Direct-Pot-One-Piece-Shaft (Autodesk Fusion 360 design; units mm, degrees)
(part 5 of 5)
work_plane "WorkPlane12" AlongDistance 50.8 ExtraOffset 0
sketch "Clamp nut top installation slot" plane through (50.8, 0, 0) normal (1, 0, 0) x axis (0, 0, -1)
  line L1 (-73, -4.3) -> (-73, -6.9)
  line L2 (-78.1, -4.3) -> (-73, -4.3)
  line L3 (-78.1, -6.9) -> (-78.1, -4.3)
  line L4 (-73, -6.9) -> (-78.1, -6.9)
extrude "Extrude12" cut sketch "Clamp nut top installation slot" along normal blind 6.7
work_plane "WorkPlane1" AlongDistance -6.8 ExtraOffset 0
sketch "Sensor clamp captive M3 nut" plane through (0, -6.8, 0) normal (0, 1, 0) x axis (1, 0, 0)
  line L1 (55.7377, -75.75) -> (57.3254, -73)
  line L2 (52.5623, -75.75) -> (55.7377, -75.75)
  line L3 (50.9746, -73) -> (52.5623, -75.75)
  line L4 (52.5623, -70.25) -> (50.9746, -73)
  line L5 (55.7377, -70.25) -> (52.5623, -70.25)
  line L6 (57.3254, -73) -> (55.7377, -70.25)
extrude "Extrude1" new body sketch "Sensor clamp captive M3 nut" along normal blind 2.4 bodies "HARDWARE Sensor clamp captive M3 nut"
work_plane "WorkPlane2" AlongDistance -6.9 ExtraOffset 0
sketch "Thread envelope" plane through (0, -6.9, 0) normal (0, 1, 0) x axis (1, 0, 0)
  circle C1 centre (54.15, -73) radius 1.5
extrude "Extrude2" cut sketch "Thread envelope" along normal blind 2.6
work_plane "WorkPlane87" AlongDistance -24 ExtraOffset 0
sketch "Rear wall around captive block nuts" plane through (-24, 0, 0) normal (1, 0, 0) x axis (0, 0, -1)
  line L1 (-38, -73.9) -> (-38, -76)
  line L2 (-59, -73.9) -> (-38, -73.9)
  line L3 (-59, -76) -> (-59, -73.9)
  line L4 (-38, -76) -> (-59, -76)
extrude "Extrude87" add sketch "Rear wall around captive block nuts" along normal blind 48
work_plane "WorkPlane88" AlongDistance 1.1 ExtraOffset 0
sketch "Extend guide nut loading access through rear wall" plane through (1.1, 0, 0) normal (1, 0, 0) x axis (0, 0, -1)
  line L1 (-40.8, -73.8) -> (-40.8, -76.1)
  line L2 (-43.4, -73.8) -> (-40.8, -73.8)
  line L3 (-43.4, -76.1) -> (-43.4, -73.8)
  line L4 (-40.8, -76.1) -> (-43.4, -76.1)
extrude "Extrude88" cut sketch "Extend guide nut loading access through rear wall" along normal blind 5.8
work_plane "WorkPlane89" AlongDistance 17.1 ExtraOffset 0
sketch "Extend guide nut loading access through rear wall (1)" plane through (17.1, 0, 0) normal (1, 0, 0) x axis (0, 0, -1)
  line L1 (-40.8, -73.8) -> (-40.8, -76.1)
  line L2 (-43.4, -73.8) -> (-40.8, -73.8)
  line L3 (-43.4, -76.1) -> (-43.4, -73.8)
  line L4 (-40.8, -76.1) -> (-43.4, -76.1)
extrude "Extrude89" cut sketch "Extend guide nut loading access through rear wall (1)" along normal blind 5.8
work_plane "WorkPlane1" AlongDistance -33.9 ExtraOffset 0
sketch "Shaft cap captured M3 nut" plane through (-33.9, 0, 0) normal (1, 0, 0) x axis (0, 0, -1)
  line L1 (-67.75, 1.5877) -> (-65, 3.1754)
  line L2 (-67.75, -1.5877) -> (-67.75, 1.5877)
  line L3 (-65, -3.1754) -> (-67.75, -1.5877)
  line L4 (-62.25, -1.5877) -> (-65, -3.1754)
  line L5 (-62.25, 1.5877) -> (-62.25, -1.5877)
  line L6 (-65, 3.1754) -> (-62.25, 1.5877)
extrude "Extrude1" new body sketch "Shaft cap captured M3 nut" along normal blind 2.4 bodies "HARDWARE Shaft cap captured M3 nut"
work_plane "WorkPlane2" AlongDistance -34 ExtraOffset 0
sketch "Thread envelope" plane through (-34, 0, 0) normal (1, 0, 0) x axis (0, 0, -1)
  circle C1 centre (-65, 0) radius 1.5
extrude "Extrude2" cut sketch "Thread envelope" along normal blind 2.6
work_plane "WorkPlane21" AlongDistance -7.1 ExtraOffset 0
sketch "Rear-loaded cam hex nut" plane through (-7.1, 0, 0) normal (1, 0, 0) x axis (0, 0, -1)
  line L1 (-42.4442, 27.1302) -> (-39.5442, 28.8045)
  line L2 (-42.4442, 23.7815) -> (-42.4442, 27.1302)
  line L3 (-39.5442, 22.1072) -> (-42.4442, 23.7815)
  line L4 (-36.6442, 23.7815) -> (-39.5442, 22.1072)
  line L5 (-36.6442, 27.1302) -> (-36.6442, 23.7815)
  line L6 (-39.5442, 28.8045) -> (-36.6442, 27.1302)
extrude "Extrude21" cut sketch "Rear-loaded cam hex nut" along normal blind 11.7
work_plane "WorkPlane1" AlongDistance 2.1 ExtraOffset 0
sketch "Cam captured M3 nut -45" plane through (2.1, 0, 0) normal (1, 0, 0) x axis (0, 0, -1)
  line L1 (-42.2942, 27.0436) -> (-39.5442, 28.6313)
  line L2 (-42.2942, 23.8681) -> (-42.2942, 27.0436)
  line L3 (-39.5442, 22.2804) -> (-42.2942, 23.8681)
  line L4 (-36.7942, 23.8681) -> (-39.5442, 22.2804)
  line L5 (-36.7942, 27.0436) -> (-36.7942, 23.8681)
  line L6 (-39.5442, 28.6313) -> (-36.7942, 27.0436)
extrude "Extrude1" new body sketch "Cam captured M3 nut -45" along normal blind 2.4 bodies "HARDWARE Cam captured M3 nut -45"
work_plane "WorkPlane2" AlongDistance 2 ExtraOffset 0
sketch "Thread envelope" plane through (2, 0, 0) normal (1, 0, 0) x axis (0, 0, -1)
  circle C1 centre (-39.5442, 25.4558) radius 1.5
extrude "Extrude2" cut sketch "Thread envelope" along normal blind 2.6
work_plane "WorkPlane22" AlongDistance -7.1 ExtraOffset 0
sketch "Rear-loaded cam hex nut (1)" plane through (-7.1, 0, 0) normal (1, 0, 0) x axis (0, 0, -1)
  line L1 (-31.9, 1.6743) -> (-29, 3.3486)
  line L2 (-31.9, -1.6743) -> (-31.9, 1.6743)
  line L3 (-29, -3.3486) -> (-31.9, -1.6743)
  line L4 (-26.1, -1.6743) -> (-29, -3.3486)
  line L5 (-26.1, 1.6743) -> (-26.1, -1.6743)
  line L6 (-29, 3.3486) -> (-26.1, 1.6743)
extrude "Extrude22" cut sketch "Rear-loaded cam hex nut (1)" along normal blind 11.7
work_plane "WorkPlane1" AlongDistance 2.1 ExtraOffset 0
sketch "Cam captured M3 nut 0" plane through (2.1, 0, 0) normal (1, 0, 0) x axis (0, 0, -1)
  line L1 (-31.75, 1.5877) -> (-29, 3.1754)
  line L2 (-31.75, -1.5877) -> (-31.75, 1.5877)
  line L3 (-29, -3.1754) -> (-31.75, -1.5877)
  line L4 (-26.25, -1.5877) -> (-29, -3.1754)
  line L5 (-26.25, 1.5877) -> (-26.25, -1.5877)
  line L6 (-29, 3.1754) -> (-26.25, 1.5877)
extrude "Extrude1" new body sketch "Cam captured M3 nut 0" along normal blind 2.4 bodies "HARDWARE Cam captured M3 nut 0"
work_plane "WorkPlane2" AlongDistance 2 ExtraOffset 0
sketch "Thread envelope" plane through (2, 0, 0) normal (1, 0, 0) x axis (0, 0, -1)
  circle C1 centre (-29, 0) radius 1.5
extrude "Extrude2" cut sketch "Thread envelope" along normal blind 2.6
work_plane "WorkPlane23" AlongDistance -7.1 ExtraOffset 0
sketch "Rear-loaded cam hex nut (2)" plane through (-7.1, 0, 0) normal (1, 0, 0) x axis (0, 0, -1)
  line L1 (-42.4442, -23.7815) -> (-39.5442, -22.1072)
  line L2 (-42.4442, -27.1302) -> (-42.4442, -23.7815)
  line L3 (-39.5442, -28.8045) -> (-42.4442, -27.1302)
  line L4 (-36.6442, -27.1302) -> (-39.5442, -28.8045)
  line L5 (-36.6442, -23.7815) -> (-36.6442, -27.1302)
  line L6 (-39.5442, -22.1072) -> (-36.6442, -23.7815)
extrude "Extrude23" cut sketch "Rear-loaded cam hex nut (2)" along normal blind 11.7
work_plane "WorkPlane1" AlongDistance 2.1 ExtraOffset 0
sketch "Cam captured M3 nut 45" plane through (2.1, 0, 0) normal (1, 0, 0) x axis (0, 0, -1)
  line L1 (-42.2942, -23.8681) -> (-39.5442, -22.2804)
  line L2 (-42.2942, -27.0436) -> (-42.2942, -23.8681)
  line L3 (-39.5442, -28.6313) -> (-42.2942, -27.0436)
  line L4 (-36.7942, -27.0436) -> (-39.5442, -28.6313)
  line L5 (-36.7942, -23.8681) -> (-36.7942, -27.0436)
  line L6 (-39.5442, -22.2804) -> (-36.7942, -23.8681)
extrude "Extrude1" new body sketch "Cam captured M3 nut 45" along normal blind 2.4 bodies "HARDWARE Cam captured M3 nut 45"
work_plane "WorkPlane2" AlongDistance 2 ExtraOffset 0
sketch "Thread envelope" plane through (2, 0, 0) normal (1, 0, 0) x axis (0, 0, -1)
  circle C1 centre (-39.5442, -25.4558) radius 1.5
extrude "Extrude2" cut sketch "Thread envelope" along normal blind 2.6
work_plane "WorkPlane24" AlongDistance 15.2 ExtraOffset 0
sketch "Rotor side-loaded clamp nut" plane through (0, 15.2, 0) normal (0, 1, 0) x axis (1, 0, 0)
  line L1 (1.6743, -67.9) -> (3.3486, -65)
  line L2 (-1.6743, -67.9) -> (1.6743, -67.9)
  line L3 (-3.3486, -65) -> (-1.6743, -67.9)
  line L4 (-1.6743, -62.1) -> (-3.3486, -65)
  line L5 (1.6743, -62.1) -> (-1.6743, -62.1)
  line L6 (3.3486, -65) -> (1.6743, -62.1)
extrude "Extrude24" cut sketch "Rotor side-loaded clamp nut" along normal blind 2.6
work_plane "WorkPlane25" AlongDistance -7.1 ExtraOffset 0
sketch "Rotor clamp nut insertion from back face" plane through (-7.1, 0, 0) normal (1, 0, 0) x axis (0, 0, -1)
  line L1 (-62.1, 17.8) -> (-62.1, 15.2)
  line L2 (-67.9, 17.8) -> (-62.1, 17.8)
  line L3 (-67.9, 15.2) -> (-67.9, 17.8)
  line L4 (-62.1, 15.2) -> (-67.9, 15.2)
extrude "Extrude25" cut sketch "Rotor clamp nut insertion from back face" along normal blind 7.1
work_plane "WorkPlane1" AlongDistance 15.3 ExtraOffset 0
sketch "Rotor clamp captured M3 nut" plane through (0, 15.3, 0) normal (0, 1, 0) x axis (1, 0, 0)
  line L1 (1.5877, -67.75) -> (3.1754, -65)
  line L2 (-1.5877, -67.75) -> (1.5877, -67.75)
  line L3 (-3.1754, -65) -> (-1.5877, -67.75)
  line L4 (-1.5877, -62.25) -> (-3.1754, -65)
  line L5 (1.5877, -62.25) -> (-1.5877, -62.25)
  line L6 (3.1754, -65) -> (1.5877, -62.25)
extrude "Extrude1" new body sketch "Rotor clamp captured M3 nut" along normal blind 2.4 bodies "HARDWARE Rotor clamp captured M3 nut"
work_plane "WorkPlane2" AlongDistance 15.2 ExtraOffset 0
sketch "Thread envelope" plane through (0, 15.2, 0) normal (0, 1, 0) x axis (1, 0, 0)
  circle C1 centre (0, -65) radius 1.5
extrude "Extrude2" cut sketch "Thread envelope" along normal blind 2.6
work_plane "WorkPlane7" AlongDistance 180 ExtraOffset 0
sketch "Small grip socket insert lead-in" plane through (0, 0, 180) normal (0, 0, 1) x axis (1, 0, 0)
  line L1 (-7.4, 1.9) -> (-7.4, 0)
  line L2 (-7.2, 2.1) -> (-7.4, 1.9)
  line L3 (-7.2, 0) -> (-7.2, 2.1)
  line L4 (-7.4, 0) -> (-7.2, 0)
  line L5 (-6.2, 0) -> (-8.4, 0)
revolve "Revolve2" sketch "Small grip socket insert lead-in" AlongAngle 360
work_plane "WorkPlane8" AlongDistance 190 ExtraOffset 0
sketch "Small grip socket insert lead-in (1)" plane through (0, 0, 190) normal (0, 0, 1) x axis (1, 0, 0)
  line L1 (-7.4, 1.9) -> (-7.4, 0)
  line L2 (-7.2, 2.1) -> (-7.4, 1.9)
  line L3 (-7.2, 0) -> (-7.2, 2.1)
  line L4 (-7.4, 0) -> (-7.2, 0)
  line L5 (-6.2, 0) -> (-8.4, 0)
revolve "Revolve3" sketch "Small grip socket insert lead-in (1)" AlongAngle 360
ground "Pin164"
ground "Pin165"
ground "Pin166"
ground "Pin167"
ground "Pin168"
ground "Pin170"
ground "Pin171"
ground "Pin172"
ground "Pin173"
ground "Pin174"
ground "Pin175"
ground "Pin176"
ground "Pin177"
ground "Pin178"
ground "Pin179"
ground "Pin180"
ground "Pin181"
ground "Pin182"
ground "Pin183"
ground "Pin184"
ground "Pin185"
ground "Pin186"
ground "Pin187"
ground "Pin188"
ground "Pin189"
ground "Pin190"
ground "Pin191"
ground "Pin192"
ground "Pin193"
ground "Pin194"
ground "Pin195"
ground "Pin196"
ground "Pin197"
ground "Pin198"
ground "Pin199"
ground "Pin200"
ground "Pin201"
ground "Pin202"
ground "Pin203"
ground "Pin204"
ground "Pin205"
ground "Pin206"
ground "Pin207"
ground "Pin208"
ground "Pin209"
ground "Pin210"
ground "Pin211"
ground "Pin216"
ground "Pin217"
ground "Pin218"
ground "Pin219"
ground "Pin220"
ground "Pin221"
ground "Pin222"
ground "Pin223"
ground "Pin224"
ground "Pin225"
ground "Pin226"
ground "Pin227"
ground "Pin228"
ground "Pin229"
ground "Pin230"
ground "Pin231"
ground "Pin232"
ground "Pin233"
ground "Pin234"
ground "Pin235"
ground "Pin236"
ground "Pin237"
ground "Pin238"
ground "Pin239"
ground "Pin242"
ground "Pin243"
ground "Pin244"
ground "Pin245"
ground "Unpin246"
ground "Unpin247"
ground "Unpin248"
ground "Unpin249"
ground "Unpin250"
ground "Unpin252"
ground "Unpin253"
ground "Unpin254"
ground "Unpin255"
ground "Unpin256"
ground "Unpin257"
ground "Unpin258"
ground "Unpin259"
ground "Unpin260"
ground "Unpin261"
ground "Unpin262"
ground "Unpin263"
ground "Unpin264"
ground "Unpin265"
ground "Unpin266"
ground "Unpin267"
ground "Unpin268"
ground "Unpin269"
ground "Unpin270"
ground "Unpin271"
ground "Unpin272"
ground "Unpin273"
ground "Unpin274"
ground "Unpin275"
ground "Unpin276"
ground "Unpin277"
ground "Unpin278"
ground "Unpin279"
ground "Unpin280"
ground "Unpin281"
ground "Unpin282"
ground "Unpin283"
ground "Unpin284"
ground "Unpin285"
ground "Unpin286"
ground "Unpin287"
ground "Unpin288"
ground "Unpin289"
ground "Unpin290"
ground "Unpin291"
ground "Unpin292"
ground "Unpin293"
ground "Unpin298"
ground "Unpin299"
ground "Unpin300"
ground "Unpin301"
ground "Unpin302"
ground "Unpin303"
ground "Unpin304"
ground "Unpin305"
ground "Unpin306"
ground "Unpin307"
ground "Unpin308"
ground "Unpin309"
ground "Unpin310"
ground "Unpin311"
ground "Unpin312"
ground "Unpin313"
ground "Unpin314"
ground "Unpin315"
ground "Unpin316"
ground "Unpin317"
ground "Unpin318"
ground "Unpin319"
ground "Unpin320"
ground "Unpin321"
ground "Unpin324"
ground "Unpin325"
ground "Unpin326"
ground "Unpin327"
position "Position1"
ground "Pin328"
ground "Pin329"
ground "Pin330"
ground "Pin331"
ground "Pin332"
ground "Pin334"
ground "Pin335"
ground "Pin336"
ground "Pin337"
ground "Pin338"
ground "Pin339"
ground "Pin340"
ground "Pin341"
ground "Pin342"
ground "Pin343"
ground "Pin344"
ground "Pin345"
ground "Pin346"
ground "Pin347"
ground "Pin348"
ground "Pin349"
ground "Pin350"
ground "Pin351"
ground "Pin352"
ground "Pin353"
ground "Pin354"
ground "Pin355"
ground "Pin356"
ground "Pin357"
ground "Pin358"
ground "Pin359"
ground "Pin360"
ground "Pin361"
ground "Pin362"
ground "Pin363"
ground "Pin364"
ground "Pin365"
ground "Pin366"
ground "Pin367"
ground "Pin368"
ground "Pin369"
ground "Pin370"
ground "Pin371"
ground "Pin372"
ground "Pin373"
ground "Pin374"
ground "Pin375"
ground "Pin380"
ground "Pin381"
ground "Pin382"
ground "Pin383"
ground "Pin384"
ground "Pin385"
ground "Pin386"
ground "Pin387"
ground "Pin388"
ground "Pin389"
ground "Pin390"
ground "Pin391"
ground "Pin392"
ground "Pin393"
ground "Pin394"
ground "Pin395"
ground "Pin396"
ground "Pin397"
ground "Pin398"
ground "Pin399"
ground "Pin400"
ground "Pin401"
ground "Pin402"
ground "Pin403"
ground "Pin406"
ground "Pin407"
ground "Pin408"
ground "Pin409"
work_plane "WorkPlane85" AlongDistance 57.9 ExtraOffset 0
sketch "Trim former insert fill flush with carriage face" plane through (57.9, 0, 0) normal (1, 0, 0) x axis (0, 0, -1)
  line L1 (-62.9, -28) -> (-62.9, -28.2)
  line L2 (-67.1, -28) -> (-62.9, -28)
  line L3 (-67.1, -28.2) -> (-67.1, -28)
  line L4 (-62.9, -28.2) -> (-67.1, -28.2)
extrude "Extrude85" cut sketch "Trim former insert fill flush with carriage face" along normal blind 4.5
work_plane "WorkPlane86" AlongDistance 57.9 ExtraOffset 0
sketch "Trim former insert fill flush with carriage face (1)" plane through (57.9, 0, 0) normal (1, 0, 0) x axis (0, 0, -1)
  line L1 (-62.9, 28.2) -> (-62.9, 28)
  line L2 (-67.1, 28.2) -> (-62.9, 28.2)
  line L3 (-67.1, 28) -> (-67.1, 28.2)
  line L4 (-62.9, 28) -> (-67.1, 28)
extrude "Extrude86" cut sketch "Trim former insert fill flush with carriage face (1)" along normal blind 4.5
ground "Unpin411"
ground "Unpin412"
ground "Unpin413"
ground "Unpin414"
ground "Unpin415"
ground "Unpin416"
ground "Unpin417"
ground "Unpin418"
ground "Unpin419"
ground "Unpin420"
ground "Unpin421"
ground "Unpin422"
ground "Unpin423"
ground "Unpin424"
ground "Unpin429"
ground "Unpin430"
ground "Unpin431"
ground "Unpin432"
ground "Unpin433"
ground "Unpin434"
ground "Unpin435"
ground "Unpin436"
ground "Unpin439"
ground "Unpin440"
ground "Unpin441"
ground "Unpin442"
work_plane "WorkPlane1" AlongDistance -37.35 ExtraOffset 0
sketch "Continuous main journal shaft" plane through (-37.35, 0, 0) normal (1, 0, 0) x axis (0, 0, -1)
  circle C1 centre (-65, 0) radius 6
extrude "Extrude1" new body sketch "Continuous main journal shaft" along normal blind 74.7 bodies "P05 One-piece shaft with continuous print flat"
work_plane "WorkPlane2" AlongDistance -23.8 ExtraOffset 0
sketch "Central load-bearing shaft" plane through (-23.8, 0, 0) normal (1, 0, 0) x axis (0, 0, -1)
  circle C1 centre (-65, 0) radius 8
extrude "Extrude2" add sketch "Central load-bearing shaft" along normal blind 47.6
work_plane "WorkPlane3" AlongDistance -23.9 ExtraOffset 0
sketch "Preserved upper D drive flat" plane through (-23.9, 0, 0) normal (1, 0, 0) x axis (0, 0, -1)
  line L1 (-56, 9) -> (-56, 6.5)
  line L2 (-74, 9) -> (-56, 9)
  line L3 (-74, 6.5) -> (-74, 9)
  line L4 (-56, 6.5) -> (-74, 6.5)
extrude "Extrude3" cut sketch "Preserved upper D drive flat" along normal blind 47.8
work_plane "WorkPlane4" AlongDistance 37.35 ExtraOffset 0
sketch "Integral retaining shoulder" plane through (37.35, 0, 0) normal (1, 0, 0) x axis (0, 0, -1)
  circle C1 centre (-65, 0) radius 10
extrude "Extrude4" add sketch "Integral retaining shoulder" along normal blind 3
work_plane "WorkPlane5" AlongDistance 37.25 ExtraOffset 0
sketch "Preserved shoulder upper flat" plane through (37.25, 0, 0) normal (1, 0, 0) x axis (0, 0, -1)
  line L1 (-54, 11) -> (-54, 6.5)
  line L2 (-76, 11) -> (-54, 11)
  line L3 (-76, 6.5) -> (-76, 11)
  line L4 (-54, 6.5) -> (-76, 6.5)
extrude "Extrude5" cut sketch "Preserved shoulder upper flat" along normal blind 3.2
work_plane "WorkPlane6" AlongDistance 40.35 ExtraOffset 0
sketch "Integral Oldham input tongue" plane through (40.35, 0, 0) normal (1, 0, 0) x axis (0, 0, -1)
  line L1 (-63, 6.5) -> (-63, -8)
  line L2 (-67, 6.5) -> (-63, 6.5)
  line L3 (-67, -8) -> (-67, 6.5)
  line L4 (-63, -8) -> (-67, -8)
extrude "Extrude6" add sketch "Integral Oldham input tongue" along normal blind 3
work_plane "WorkPlane7" AlongDistance -37.5 ExtraOffset 0
sketch "Continuous underside print bed flat" plane through (-37.5, 0, 0) normal (1, 0, 0) x axis (0, 0, -1)
  line L1 (-54, -4.2) -> (-54, -10.2)
  line L2 (-76, -4.2) -> (-54, -4.2)
  line L3 (-76, -10.2) -> (-76, -4.2)
  line L4 (-54, -10.2) -> (-76, -10.2)
extrude "Extrude7" cut sketch "Continuous underside print bed flat" along normal blind 81
work_plane "WorkPlane8" AlongDistance -37.45 ExtraOffset 0
sketch "End cap M3 passage" plane through (-37.45, 0, 0) normal (1, 0, 0) x axis (0, 0, -1)
  circle C1 centre (-65, 0) radius 1.7
extrude "Extrude8" cut sketch "End cap M3 passage" along normal blind 6.8
work_plane "WorkPlane9" AlongDistance -37.45 ExtraOffset 0
sketch "Support-free screw-passage crown" plane through (-37.45, 0, 0) normal (1, 0, 0) x axis (0, 0, -1)
  line L1 (-66.2021, 1.2021) -> (-63.7979, 1.2021)
  line L2 (-65, 2.4042) -> (-66.2021, 1.2021)
  line L3 (-63.7979, 1.2021) -> (-65, 2.4042)
extrude "Extrude9" cut sketch "Support-free screw-passage crown" along normal blind 6.8
work_plane "WorkPlane10" AlongDistance -34 ExtraOffset 0
sketch "Captured cap nut pocket" plane through (-34, 0, 0) normal (1, 0, 0) x axis (0, 0, -1)
  line L1 (-67.9, 1.6743) -> (-65, 3.3486)
  line L2 (-67.9, -1.6743) -> (-67.9, 1.6743)
  line L3 (-65, -3.3486) -> (-67.9, -1.6743)
  line L4 (-62.1, -1.6743) -> (-65, -3.3486)
  line L5 (-62.1, 1.6743) -> (-62.1, -1.6743)
  line L6 (-65, 3.3486) -> (-62.1, 1.6743)
extrude "Extrude10" cut sketch "Captured cap nut pocket" along normal blind 2.6
work_plane "WorkPlane11" AlongDistance -34 ExtraOffset 0
sketch "Nut installation from bed flat" plane through (-34, 0, 0) normal (1, 0, 0) x axis (0, 0, -1)
  line L1 (-62.1, 0) -> (-62.1, -4.3)
  line L2 (-67.9, 0) -> (-62.1, 0)
  line L3 (-67.9, -4.3) -> (-67.9, 0)
  line L4 (-62.1, -4.3) -> (-67.9, -4.3)
extrude "Extrude11" cut sketch "Nut installation from bed flat" along normal blind 2.6
position "Position2"
work_plane "WorkPlane12" AlongDistance 40.35 ExtraOffset 0
sketch "Restore positive tongue contact radius" plane through (40.35, 0, 0) normal (1, 0, 0) x axis (0, 0, -1)
  line L1 (-63, 8) -> (-63, 6.4)
  line L2 (-67, 8) -> (-63, 8)
  line L3 (-67, 6.4) -> (-67, 8)
  line L4 (-63, 6.4) -> (-67, 6.4)
extrude "Extrude12" add sketch "Restore positive tongue contact radius" along normal blind 3
work_plane "WorkPlane1" AlongDistance 7 ExtraOffset 0
sketch "Nine gate roller compensated cam" plane through (7, 0, 0) normal (1, 0, 0) x axis (0, 0, -1)
  line L1 (-39.9147, 41.3266) -> (-40.1394, 41.4106)
  line L2 (-39.702, 41.2471) -> (-39.9147, 41.3266)
  line L3 (-39.5019, 41.1715) -> (-39.702, 41.2471)
  line L4 (-39.3145, 41.0995) -> (-39.5019, 41.1715)
  line L5 (-39.1399, 41.0307) -> (-39.3145, 41.0995)
  line L6 (-38.978, 40.9647) -> (-39.1399, 41.0307)
  line L7 (-38.8282, 40.9014) -> (-38.978, 40.9647)
  line L8 (-38.6902, 40.8404) -> (-38.8282, 40.9014)
  line L9 (-38.5632, 40.7815) -> (-38.6902, 40.8404)
  line L10 (-38.4461, 40.7243) -> (-38.5632, 40.7815)
  line L11 (-38.3379, 40.6685) -> (-38.4461, 40.7243)
  line L12 (-38.2374, 40.6136) -> (-38.3379, 40.6685)
  line L13 (-38.143, 40.559) -> (-38.2374, 40.6136)
  line L14 (-38.0534, 40.5041) -> (-38.143, 40.559)
  line L15 (-37.967, 40.4479) -> (-38.0534, 40.5041)
  line L16 (-37.8822, 40.3896) -> (-37.967, 40.4479)
  line L17 (-37.7976, 40.3281) -> (-37.8822, 40.3896)
  line L18 (-37.7117, 40.2623) -> (-37.7976, 40.3281)
  line L19 (-37.6233, 40.191) -> (-37.7117, 40.2623)
  line L20 (-37.5313, 40.1132) -> (-37.6233, 40.191)
  line L21 (-37.4347, 40.0277) -> (-37.5313, 40.1132)
  line L22 (-37.3326, 39.9337) -> (-37.4347, 40.0277)
  line L23 (-37.2244, 39.8302) -> (-37.3326, 39.9337)
  line L24 (-37.1095, 39.7168) -> (-37.2244, 39.8302)
  line L25 (-36.9873, 39.593) -> (-37.1095, 39.7168)
  line L26 (-36.8575, 39.4584) -> (-36.9873, 39.593)
  line L27 (-36.7197, 39.3131) -> (-36.8575, 39.4584)
  line L28 (-36.5736, 39.1573) -> (-36.7197, 39.3131)
  line L29 (-36.4189, 38.9914) -> (-36.5736, 39.1573)
  line L30 (-36.2555, 38.8158) -> (-36.4189, 38.9914)
  line L31 (-36.083, 38.6314) -> (-36.2555, 38.8158)
  line L32 (-35.9014, 38.4391) -> (-36.083, 38.6314)
  line L33 (-35.7107, 38.24) -> (-35.9014, 38.4391)
  line L34 (-35.511, 38.0353) -> (-35.7107, 38.24)
  line L35 (-35.3023, 37.8264) -> (-35.511, 38.0353)
  line L36 (-35.0852, 37.6148) -> (-35.3023, 37.8264)
  line L37 (-34.8601, 37.4018) -> (-35.0852, 37.6148)
  line L38 (-34.6279, 37.1891) -> (-34.8601, 37.4018)
  line L39 (-34.3896, 36.9781) -> (-34.6279, 37.1891)
  line L40 (-34.1462, 36.7701) -> (-34.3896, 36.9781)
  line L41 (-33.8992, 36.5666) -> (-34.1462, 36.7701)
  line L42 (-33.6499, 36.3685) -> (-33.8992, 36.5666)
  line L43 (-33.4001, 36.1767) -> (-33.6499, 36.3685)
  line L44 (-33.1514, 35.9921) -> (-33.4001, 36.1767)
  line L45 (-32.9052, 35.815) -> (-33.1514, 35.9921)
  line L46 (-32.6634, 35.6459) -> (-32.9052, 35.815)
  line L47 (-32.4272, 35.4847) -> (-32.6634, 35.6459)
  line L48 (-32.1981, 35.3315) -> (-32.4272, 35.4847)
  line L49 (-31.9773, 35.1861) -> (-32.1981, 35.3315)
  line L50 (-31.7658, 35.0482) -> (-31.9773, 35.1861)
  line L51 (-31.5646, 34.9176) -> (-31.7658, 35.0482)
  line L52 (-31.3742, 34.7939) -> (-31.5646, 34.9176)
  line L53 (-31.1952, 34.6768) -> (-31.3742, 34.7939)
  line L54 (-31.0278, 34.5659) -> (-31.1952, 34.6768)
  line L55 (-30.8723, 34.4609) -> (-31.0278, 34.5659)
  line L56 (-30.7284, 34.3615) -> (-30.8723, 34.4609)
  line L57 (-30.5959, 34.2673) -> (-30.7284, 34.3615)
  line L58 (-30.4744, 34.1778) -> (-30.5959, 34.2673)
  line L59 (-30.3631, 34.0928) -> (-30.4744, 34.1778)
  line L60 (-30.2612, 34.0116) -> (-30.3631, 34.0928)
  line L61 (-30.1677, 33.9337) -> (-30.2612, 34.0116)
  line L62 (-30.0814, 33.8584) -> (-30.1677, 33.9337)
  line L63 (-30.0011, 33.7847) -> (-30.0814, 33.8584)
  line L64 (-29.9255, 33.7117) -> (-30.0011, 33.7847)
  line L65 (-29.8532, 33.6381) -> (-29.9255, 33.7117)
  line L66 (-29.7831, 33.5629) -> (-29.8532, 33.6381)
  line L67 (-29.7138, 33.4845) -> (-29.7831, 33.5629)
  line L68 (-29.6442, 33.4017) -> (-29.7138, 33.4845)
  line L69 (-29.5733, 33.313) -> (-29.6442, 33.4017)
  line L70 (-29.5004, 33.217) -> (-29.5733, 33.313)
  line L71 (-29.4245, 33.1127) -> (-29.5004, 33.217)
  line L72 (-29.3452, 32.9988) -> (-29.4245, 33.1127)
  line L73 (-29.262, 32.8744) -> (-29.3452, 32.9988)
  line L74 (-29.1743, 32.7388) -> (-29.262, 32.8744)
  line L75 (-29.0818, 32.5914) -> (-29.1743, 32.7388)
  line L76 (-28.9842, 32.4319) -> (-29.0818, 32.5914)
  line L77 (-28.8811, 32.2603) -> (-28.9842, 32.4319)
  line L78 (-28.7722, 32.0765) -> (-28.8811, 32.2603)
  line L79 (-28.6571, 31.881) -> (-28.7722, 32.0765)
  line L80 (-28.5355, 31.6743) -> (-28.6571, 31.881)
  line L81 (-28.4071, 31.4569) -> (-28.5355, 31.6743)
  line L82 (-28.2715, 31.2299) -> (-28.4071, 31.4569)
  line L83 (-28.1284, 30.9942) -> (-28.2715, 31.2299)
  line L84 (-27.9776, 30.7512) -> (-28.1284, 30.9942)
  line L85 (-27.8191, 30.5021) -> (-27.9776, 30.7512)
  line L86 (-27.653, 30.2484) -> (-27.8191, 30.5021)
  line L87 (-27.4793, 29.9918) -> (-27.653, 30.2484)
  line L88 (-27.2987, 29.7338) -> (-27.4793, 29.9918)
  line L89 (-27.1116, 29.4762) -> (-27.2987, 29.7338)
  line L90 (-26.919, 29.2205) -> (-27.1116, 29.4762)
  line L91 (-26.7219, 28.9683) -> (-26.919, 29.2205)
  line L92 (-26.5215, 28.721) -> (-26.7219, 28.9683)
  line L93 (-26.3191, 28.4797) -> (-26.5215, 28.721)
  line L94 (-26.1162, 28.2456) -> (-26.3191, 28.4797)
  line L95 (-25.9142, 28.0195) -> (-26.1162, 28.2456)
  line L96 (-25.7147, 27.802) -> (-25.9142, 28.0195)
  line L97 (-25.519, 27.5935) -> (-25.7147, 27.802)
  line L98 (-25.3285, 27.3943) -> (-25.519, 27.5935)
  line L99 (-25.1444, 27.2046) -> (-25.3285, 27.3943)
  line L100 (-24.9678, 27.0242) -> (-25.1444, 27.2046)
  line L101 (-24.7996, 26.8531) -> (-24.9678, 27.0242)
  line L102 (-24.6405, 26.6912) -> (-24.7996, 26.8531)
  line L103 (-24.491, 26.5381) -> (-24.6405, 26.6912)
  line L104 (-24.3517, 26.3936) -> (-24.491, 26.5381)
  line L105 (-24.2225, 26.2575) -> (-24.3517, 26.3936)
  line L106 (-24.1036, 26.1293) -> (-24.2225, 26.2575)
  line L107 (-23.9947, 26.0086) -> (-24.1036, 26.1293)
  line L108 (-23.8954, 25.895) -> (-23.9947, 26.0086)
  line L109 (-23.8051, 25.7879) -> (-23.8954, 25.895)
  line L110 (-23.7232, 25.6866) -> (-23.8051, 25.7879)
  line L111 (-23.6487, 25.5903) -> (-23.7232, 25.6866)
  line L112 (-23.5808, 25.498) -> (-23.6487, 25.5903)
  line L113 (-23.5184, 25.4087) -> (-23.5808, 25.498)
  line L114 (-23.4603, 25.321) -> (-23.5184, 25.4087)
  line L115 (-23.4057, 25.2336) -> (-23.4603, 25.321)
  line L116 (-23.3535, 25.1449) -> (-23.4057, 25.2336)
  line L117 (-23.3028, 25.0534) -> (-23.3535, 25.1449)
  line L118 (-23.2528, 24.9575) -> (-23.3028, 25.0534)
  line L119 (-23.2029, 24.8556) -> (-23.2528, 24.9575)
  line L120 (-23.1524, 24.7461) -> (-23.2029, 24.8556)
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extrude "Extrude1" new body sketch "Nine gate roller compensated cam" along normal blind 8 bodies "P08 Cam 9 gates Class 323 - strong center and Emergency"
work_plane "WorkPlane2" AlongDistance 6.9 ExtraOffset 0
sketch "Cam screw clearance" plane through (6.9, 0, 0) normal (1, 0, 0) x axis (0, 0, -1)
  circle C1 centre (-39.5442, 25.4558) radius 1.7
extrude "Extrude2" cut sketch "Cam screw clearance" along normal blind 8.2
work_plane "WorkPlane3" AlongDistance 12 ExtraOffset 0
sketch "Cam head recess" plane through (12, 0, 0) normal (1, 0, 0) x axis (0, 0, -1)
  circle C1 centre (-39.5442, 25.4558) radius 3.1
extrude "Extrude3" cut sketch "Cam head recess" along normal blind 3.1
work_plane "WorkPlane4" AlongDistance 6.9 ExtraOffset 0
sketch "Cam screw clearance (1)" plane through (6.9, 0, 0) normal (1, 0, 0) x axis (0, 0, -1)
  circle C1 centre (-29, 0) radius 1.7
extrude "Extrude4" cut sketch "Cam screw clearance (1)" along normal blind 8.2
work_plane "WorkPlane5" AlongDistance 12 ExtraOffset 0
sketch "Cam head recess (1)" plane through (12, 0, 0) normal (1, 0, 0) x axis (0, 0, -1)
  circle C1 centre (-29, 0) radius 3.1
extrude "Extrude5" cut sketch "Cam head recess (1)" along normal blind 3.1
work_plane "WorkPlane6" AlongDistance 6.9 ExtraOffset 0
sketch "Cam screw clearance (2)" plane through (6.9, 0, 0) normal (1, 0, 0) x axis (0, 0, -1)
  circle C1 centre (-39.5442, -25.4558) radius 1.7
extrude "Extrude6" cut sketch "Cam screw clearance (2)" along normal blind 8.2
work_plane "WorkPlane7" AlongDistance 12 ExtraOffset 0
sketch "Cam head recess (2)" plane through (12, 0, 0) normal (1, 0, 0) x axis (0, 0, -1)
  circle C1 centre (-39.5442, -25.4558) radius 3.1
extrude "Extrude7" cut sketch "Cam head recess (2)" along normal blind 3.1
work_plane "WorkPlane8" AlongDistance 14.6 ExtraOffset 0
sketch "Emergency endpoint E marker" plane through (14.6, 0, 0) normal (1, 0, 0) x axis (0, 0, -1)
  line L1 (-35.6601, -31.7399) -> (-35.6601, -34.1399)
  line L2 (-36.2601, -31.7399) -> (-35.6601, -31.7399)
  line L3 (-36.2601, -33.5399) -> (-36.2601, -31.7399)
  line L4 (-37.0601, -33.5399) -> (-36.2601, -33.5399)
  line L5 (-37.0601, -32.0399) -> (-37.0601, -33.5399)
  line L6 (-37.6601, -32.0399) -> (-37.0601, -32.0399)
  line L7 (-37.6601, -33.5399) -> (-37.6601, -32.0399)
  line L8 (-38.4601, -33.5399) -> (-37.6601, -33.5399)
  line L9 (-38.4601, -31.7399) -> (-38.4601, -33.5399)
  line L10 (-39.0601, -31.7399) -> (-38.4601, -31.7399)
  line L11 (-39.0601, -34.1399) -> (-39.0601, -31.7399)
  line L12 (-35.6601, -34.1399) -> (-39.0601, -34.1399)
extrude "Extrude8" cut sketch "Emergency endpoint E marker" along normal blind 0.5
position "Position3"
ground "Pin443"
as_built_joint "As-built19"
as_built_joint "As-built20"
as_built_joint "As-built21" RotateMinimum -52 RotateMaximum 52
as_built_joint "As-built22" RotateMinimum -6 RotateMaximum 1
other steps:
create_component "CreateComponent1"
create_component "CreateComponent2"
create_component "CreateComponent3"
create_component "CreateComponent4"
create_component "CreateComponent5"
create_component "CreateComponent7"
create_component "CreateComponent8"
create_component "CreateComponent9"
create_component "CreateComponent10"
create_component "CreateComponent11"
create_component "CreateComponent12"
create_component "CreateComponent13"
create_component "CreateComponent14"
create_component "CreateComponent16"
create_component "CreateComponent28"
create_component "CreateComponent29"
create_component "CreateComponent49"
create_component "CreateComponent89"
create_component "CreateComponent90"
create_component "CreateComponent140"
create_component "CreateComponent141"
create_component "CreateComponent142"
create_component "CreateComponent143"
create_component "CreateComponent144"
create_component "CreateComponent145"
create_component "CreateComponent146"
create_component "CreateComponent147"
create_component "CreateComponent148"
create_component "CreateComponent149"
create_component "CreateComponent150"
create_component "CreateComponent151"
create_component "CreateComponent152"
create_component "CreateComponent153"
create_component "CreateComponent154"
create_component "CreateComponent155"
create_component "CreateComponent156"
create_component "CreateComponent157"
create_component "CreateComponent158"
create_component "CreateComponent159"
create_component "CreateComponent160"
create_component "CreateComponent161"
create_component "CreateComponent162"
create_component "CreateComponent163"
create_component "CreateComponent164"
create_component "CreateComponent165"
create_component "CreateComponent166"
create_component "CreateComponent167"
create_component "CreateComponent175"
create_component "CreateComponent176"
create_component "CreateComponent177"
create_component "CreateComponent178"
create_component "CreateComponent179"
create_component "CreateComponent180"
create_component "CreateComponent181"
create_component "CreateComponent182"
create_component "CreateComponent183"
create_component "CreateComponent184"
create_component "CreateComponent185"
create_component "CreateComponent186"
create_component "CreateComponent187"
create_component "CreateComponent188"
create_component "CreateComponent189"
create_component "CreateComponent190"
create_component "CreateComponent191"
create_component "CreateComponent192"
create_component "CreateComponent193"
create_component "CreateComponent194"
create_component "CreateComponent195"
create_component "CreateComponent196"
create_component "CreateComponent197"
create_component "CreateComponent198"
create_component "CreateComponent201"
create_component "CreateComponent202"
create_component "CreateComponent203"
create_component "CreateComponent204"
create_component "CreateComponent205"
create_component "CreateComponent206"
named bodies: "P01 Left rail sideplate", "P02 Right rail sideplate", "P03 Left flanged journal bush", "P04 Right bush lower half", "P06 Shaft retaining cap", "P07 Integral lever rotor and cam carrier", "P08 Cam 7 gates - stable endpoints", "P08 Cam 5 gates - stable endpoints", "P08 Cam 3 gates - stable endpoints", "P09 Grip insert half", "P10 Grip screw half", "P11 Forked roller follower", "P13 Spring reaction crossblock", "P21 Follower left axial spacer", "P22 Follower right axial spacer", "HARDWARE Roller axle M3 nut", "P23 Left rotor thrust spacer", "P24 Right rotor thrust spacer", "HARDWARE Rail M5x14 DIN912 (-30, -1)", "HARDWARE Rail M5x14 DIN912 (-30, 1)", "HARDWARE Rail M5x14 DIN912 (30, -1)", "HARDWARE Rail M5x14 DIN912 (30, 1)", "P25 Captured printed pivot lower half", "P26 Captured printed pivot upper half", "HARDWARE Grip M3x20 cap head 180", "HARDWARE Grip M3x20 cap head 190", "HARDWARE Stop M3x20 cap head -1", "HARDWARE Stop M3 plain captive nut -1", "HARDWARE Stop M3x20 cap head 1", "HARDWARE Stop M3 plain captive nut 1", "HARDWARE 623ZZ roller bearing at 8", "HARDWARE 623ZZ roller bearing at 12", "P27 Printed guide sleeve 4", "HARDWARE Cup guide M3x12 4", "P27 Printed guide sleeve 20", "HARDWARE Cup guide M3x12 20", "P14 Captive spring cup for 9 mm spring", "P15 Recessed preload limit collar 1 mm", "HARDWARE Preload M3x20 cap head", "REFERENCE Stock spring OD9 wire1 free20 - rate and solid height assumed", "P16 Compact adjustable RK097 mount", "HARDWARE Compact carriage M3x12 -1", "HARDWARE Compact carriage M3x12 1", "P18 Compact floating coupling disc", "P19 Compact one-piece sensor clamp", "HARDWARE Compact sensor clamp M3x16", "HARDWARE Main shaft cap M3x8 cap head", "HARDWARE Cam M3x10 cap head -45", "HARDWARE Cam M3x10 cap head 0", "HARDWARE Cam M3x10 cap head 45", "HARDWARE Roller axle M3x20 cap head", "HARDWARE Crossblock M3x20 cap head (-62, -1)", "HARDWARE Crossblock M3x20 cap head (-62, 1)", "HARDWARE Crossblock M3x20 cap head (-70, -1)", "HARDWARE Crossblock M3x20 cap head (-70, 1)", "HARDWARE Rotor clamp M3x16 cap head", "P04 Right bush upper half", "HARDWARE Pot supplied washer assumed", "HARDWARE Pot supplied M7 nut assumed", "HARDWARE Carriage captured M3 -1"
